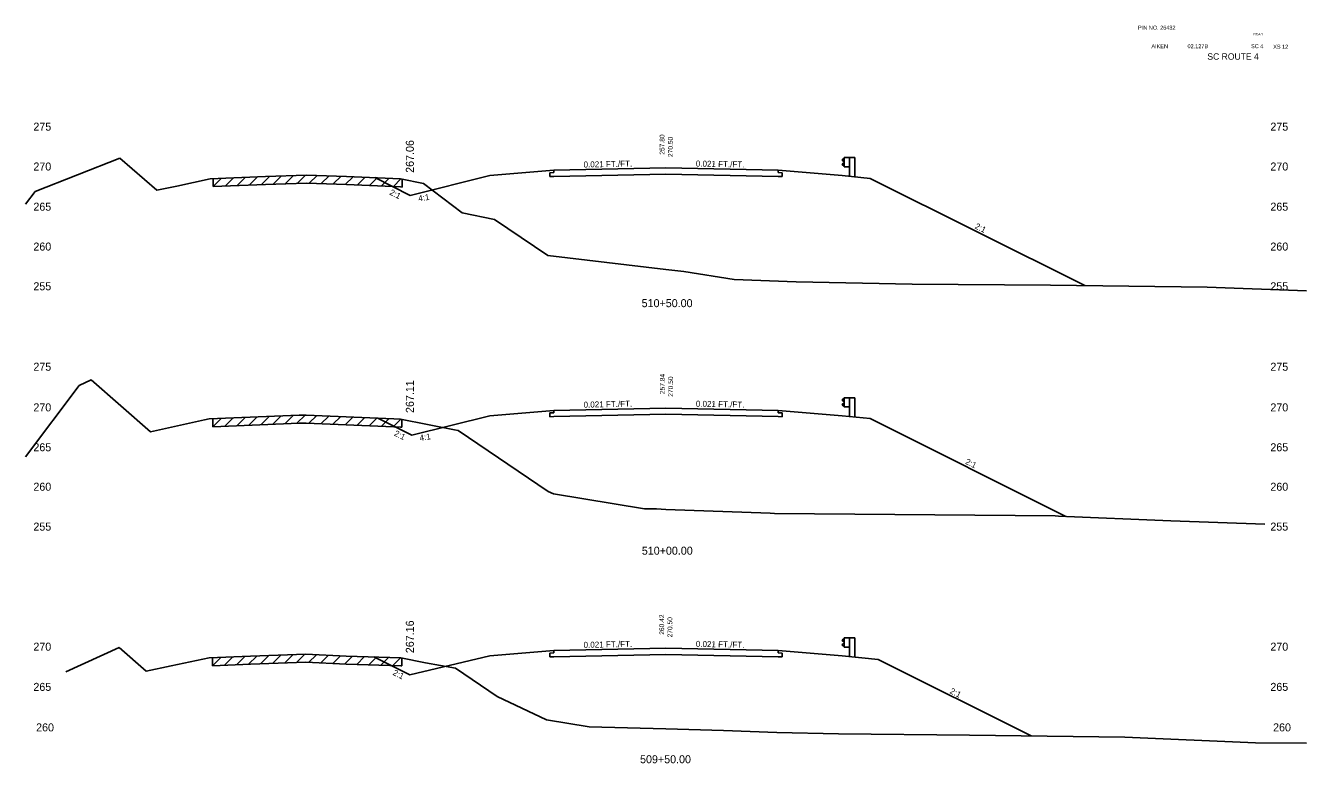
# Model space of a CAD drawing. Extents: x 883 to 1160, y 1002 to 4323.
# Drawn here: x 1000 to 1160, y 2276.1 to 2368.3 of the extents above; entities that cross this region are included whole.
import ezdxf

# ---------------------------------------------------------------- set-up
doc = ezdxf.new("R2010")
doc.units = 0
for name, color, linetype in [('Level 1', 7, 'Continuous'), ('Level 10', 7, 'Continuous'), ('Level 11', 7, 'Continuous'), ('Level 12', 7, 'Continuous'), ('Level 24', 7, 'Continuous'), ('Level 3', 7, 'Continuous'), ('Level 32', 7, 'Continuous'), ('Level 33', 7, 'Continuous'), ('Level 59', 7, 'Continuous'), ('Level 6', 7, 'Continuous'), ('Level 60', 7, 'Continuous'), ('Level 61', 7, 'Continuous'), ('Level 7', 7, 'Continuous')]:
    doc.layers.add(name, color=color, linetype=linetype)

msp = doc.modelspace()

# ---------------------------------------------------------------- linework, layer by layer
at = {"layer": 'Level 11'}
for p, q in [((1066, 2349.91), (1065.5, 2349.9)), ((1065.5, 2349.9), (1065.5, 2349.42)), ((1065.5, 2349.42), (1066, 2349.43)), ((1066, 2350.21), (1066, 2349.91)), ((1094, 2349.91), (1094, 2350.21)), ((1094.5, 2349.9), (1094, 2349.91)), ((1094, 2349.43), (1094.5, 2349.42)), ((1094.5, 2349.42), (1094.5, 2349.9)), ((1066, 2320.21), (1066, 2319.91)), ((1094, 2319.91), (1094, 2320.21)), ((1066, 2319.91), (1065.5, 2319.9)), ((1065.5, 2319.9), (1065.5, 2319.42)), ((1065.5, 2319.42), (1066, 2319.43)), ((1094.5, 2319.9), (1094, 2319.91)), ((1094, 2319.43), (1094.5, 2319.42)), ((1094.5, 2319.42), (1094.5, 2319.9)), ((1066, 2289.91), (1065.5, 2289.9)), ((1065.5, 2289.9), (1065.5, 2289.42)), ((1066, 2290.21), (1066, 2289.91)), ((1094, 2289.91), (1094, 2290.21)), ((1094.5, 2289.9), (1094, 2289.91)), ((1094.5, 2289.42), (1094.5, 2289.9)), ((1065.5, 2289.42), (1066, 2289.43)), ((1094, 2289.43), (1094.5, 2289.42))]:
    msp.add_line(p, q, dxfattribs=at)
at = {"layer": 'Level 12'}
for p, q in [((1080, 2349.72), (1066, 2349.43)), ((1094, 2349.43), (1080, 2349.72)), ((1080, 2319.72), (1066, 2319.43)), ((1094, 2319.43), (1080, 2319.72)), ((1080, 2289.72), (1066, 2289.43)), ((1094, 2289.43), (1080, 2289.72))]:
    msp.add_line(p, q, dxfattribs=at)
at = {"layer": 'Level 24'}
for p, q in [((1102.27, 2351.72), (1102, 2351.52)), ((1102, 2351.52), (1102, 2351.47)), ((1102, 2351.47), (1102.27, 2351.27)), ((1102, 2350.95), (1102.27, 2351.15)), ((1102, 2350.9), (1102, 2350.95)), ((1102.27, 2350.7), (1102, 2350.9)), ((1102.27, 2350.63), (1102.27, 2351.79)), ((1102.27, 2351.79), (1102.94, 2351.79)), ((1102.27, 2350.63), (1102.94, 2350.63)), ((1102.94, 2351.79), (1102.94, 2349.45)), ((1102.94, 2351.79), (1103.6, 2351.79)), ((1103.6, 2351.79), (1103.6, 2349.38)), ((1102.27, 2321.72), (1102, 2321.52)), ((1102.27, 2320.63), (1102.27, 2321.79)), ((1102.27, 2321.79), (1102.94, 2321.79)), ((1102.94, 2321.79), (1102.94, 2319.45)), ((1102.94, 2321.79), (1103.6, 2321.79)), ((1103.6, 2321.79), (1103.6, 2319.38)), ((1102, 2321.52), (1102, 2321.47)), ((1102, 2321.47), (1102.27, 2321.27)), ((1102, 2320.95), (1102.27, 2321.15)), ((1102, 2320.9), (1102, 2320.95)), ((1102.27, 2320.7), (1102, 2320.9)), ((1102.27, 2320.63), (1102.94, 2320.63)), ((1102.27, 2291.72), (1102, 2291.52)), ((1102, 2291.52), (1102, 2291.47)), ((1102, 2291.47), (1102.27, 2291.27)), ((1102.27, 2290.63), (1102.27, 2291.79)), ((1102.27, 2291.79), (1102.94, 2291.79)), ((1102.94, 2291.79), (1102.94, 2289.45)), ((1102.94, 2291.79), (1103.6, 2291.79)), ((1103.6, 2291.79), (1103.6, 2289.38)), ((1102, 2290.95), (1102.27, 2291.15)), ((1102, 2290.9), (1102, 2290.95)), ((1102.27, 2290.7), (1102, 2290.9)), ((1102.27, 2290.63), (1102.94, 2290.63))]:
    msp.add_line(p, q, dxfattribs=at)
at = {"layer": 'Level 59'}
for p, q in [((1066, 2350.21), (1080, 2350.5)), ((1080, 2350.5), (1094, 2350.21)), ((1066, 2320.21), (1080, 2320.5)), ((1080, 2320.5), (1094, 2320.21)), ((1066, 2290.21), (1080, 2290.5)), ((1080, 2290.5), (1094, 2290.21))]:
    msp.add_line(p, q, dxfattribs=at)
at = {"layer": 'Level 6'}
for p, q in [((1058, 2349.54), (1066, 2350.21)), ((1094, 2350.21), (1102, 2349.54)), ((1102, 2349.54), (1105.5, 2349.19)), ((1058, 2319.54), (1066, 2320.21)), ((1094, 2320.21), (1102, 2319.54)), ((1102, 2319.54), (1105.5, 2319.19)), ((1058, 2289.54), (1066, 2290.21)), ((1094, 2290.21), (1102, 2289.54)), ((1102, 2289.54), (1106.5, 2289.09))]:
    msp.add_line(p, q, dxfattribs=at)
at = {"layer": 'Level 60'}
for p, q in [((1001.18, 2347.53), (1011.79, 2351.72)), ((1011.79, 2351.72), (1016.39, 2347.7)), ((1018.89, 2348.23), (1023.07, 2349.14)), ((1023.07, 2349.14), (1029.98, 2349.42)), ((1029.98, 2349.42), (1035.08, 2349.6)), ((1035.08, 2349.6), (1040.09, 2349.43)), ((1040.09, 2349.43), (1046.84, 2349.13)), ((1046.84, 2349.13), (1049.69, 2348.56)), ((1000, 2345.96), (1001.18, 2347.53)), ((1016.39, 2347.7), (1018.89, 2348.23)), ((1049.69, 2348.56), (1054.54, 2344.88)), ((1054.54, 2344.88), (1058.59, 2344.06)), ((1058.59, 2344.06), (1065.23, 2339.56)), ((1065.23, 2339.56), (1080, 2337.81)), ((1080, 2337.81), (1082.21, 2337.54)), ((1082.21, 2337.54), (1088.53, 2336.54)), ((1088.53, 2336.54), (1096.28, 2336.28)), ((1096.28, 2336.28), (1110.74, 2335.97)), ((1110.74, 2335.97), (1128.03, 2335.84)), ((1128.03, 2335.84), (1147.59, 2335.59)), ((1147.59, 2335.59), (1160, 2335.12)), ((1000, 2314.41), (1006.68, 2323.32)), ((1006.68, 2323.32), (1008.19, 2324.02)), ((1008.19, 2324.02), (1015.59, 2317.54)), ((1015.59, 2317.54), (1022.35, 2319.03)), ((1022.35, 2319.03), (1022.95, 2319.15)), ((1022.95, 2319.15), (1034.17, 2319.6)), ((1034.17, 2319.6), (1035.03, 2319.63)), ((1035.03, 2319.63), (1045.99, 2319.14)), ((1045.99, 2319.14), (1046.85, 2319.12)), ((1046.85, 2319.12), (1053.58, 2317.78)), ((1053.58, 2317.78), (1054.02, 2317.7)), ((1054.02, 2317.7), (1065.29, 2310.07)), ((1065.29, 2310.07), (1065.93, 2309.77)), ((1065.93, 2309.77), (1077.32, 2307.93)), ((1077.32, 2307.93), (1078.81, 2307.89)), ((1078.81, 2307.89), (1080, 2307.84)), ((1080, 2307.84), (1093.01, 2307.36)), ((1093.01, 2307.36), (1093.55, 2307.34)), ((1093.55, 2307.34), (1128.62, 2307.02)), ((1128.62, 2307.02), (1129.03, 2307.01)), ((1129.03, 2307.01), (1143.08, 2306.43)), ((1143.08, 2306.43), (1154.81, 2305.98)), ((1005.03, 2287.54), (1011.67, 2290.6)), ((1011.67, 2290.6), (1015.07, 2287.62)), ((1028.09, 2289.5), (1035.01, 2289.74)), ((1035.01, 2289.74), (1040.06, 2289.52)), ((1015.07, 2287.62), (1018.19, 2288.3)), ((1018.19, 2288.3), (1022.92, 2289.29)), ((1022.92, 2289.29), (1028.09, 2289.5)), ((1040.06, 2289.52), (1046.86, 2289.3)), ((1046.86, 2289.3), (1049.97, 2288.68)), ((1049.97, 2288.68), (1053.7, 2288)), ((1053.7, 2288), (1058.92, 2284.46)), ((1058.92, 2284.46), (1065.08, 2281.55)), ((1065.08, 2281.55), (1070.39, 2280.69)), ((1070.39, 2280.69), (1080, 2280.42)), ((1080, 2280.42), (1087.2, 2280.21)), ((1087.2, 2280.21), (1093.83, 2279.97)), ((1093.83, 2279.97), (1101.55, 2279.8)), ((1101.55, 2279.8), (1117.91, 2279.65)), ((1117.91, 2279.65), (1137.3, 2279.38)), ((1137.3, 2279.38), (1153.66, 2278.7)), ((1153.66, 2278.7), (1160, 2278.65))]:
    msp.add_line(p, q, dxfattribs=at)
at = {"layer": 'Level 61'}
for p, q in [((1024.48, 2349.2), (1023.44, 2348.16)), ((1023.44, 2349.16), (1023.44, 2348.16)), ((1025.98, 2349.26), (1024.94, 2348.22)), ((1027.48, 2349.32), (1026.44, 2348.28)), ((1028.98, 2349.38), (1027.94, 2348.34)), ((1030.48, 2349.44), (1029.44, 2348.4)), ((1031.98, 2349.49), (1030.94, 2348.45)), ((1033.48, 2349.54), (1032.44, 2348.51)), ((1034.98, 2349.6), (1033.94, 2348.56)), ((1036.41, 2349.56), (1035.44, 2348.59)), ((1037.91, 2349.5), (1036.94, 2348.54)), ((1039.41, 2349.45), (1038.44, 2348.49)), ((1040.9, 2349.39), (1039.94, 2348.44)), ((1042.4, 2349.33), (1041.44, 2348.37)), ((1043.9, 2349.26), (1042.94, 2348.3)), ((1045.4, 2349.2), (1044.44, 2348.24)), ((1046.89, 2349.12), (1045.94, 2348.17)), ((1047.02, 2348.1), (1047.02, 2349.1)), ((1023.44, 2348.16), (1029.98, 2348.42)), ((1029.98, 2348.42), (1035.08, 2348.6)), ((1035.08, 2348.6), (1040.09, 2348.43)), ((1040.09, 2348.43), (1046.84, 2348.13)), ((1046.84, 2348.13), (1047.02, 2348.1)), ((1024.44, 2319.21), (1023.4, 2318.17)), ((1023.4, 2319.17), (1023.4, 2318.17)), ((1023.4, 2318.17), (1034.17, 2318.6)), ((1025.94, 2319.27), (1024.9, 2318.23)), ((1027.44, 2319.33), (1026.4, 2318.29)), ((1028.94, 2319.39), (1027.9, 2318.35)), ((1030.44, 2319.45), (1029.4, 2318.41)), ((1031.94, 2319.51), (1030.9, 2318.47)), ((1033.44, 2319.57), (1032.4, 2318.53)), ((1034.94, 2319.62), (1033.9, 2318.59)), ((1034.17, 2318.6), (1035.03, 2318.63)), ((1035.03, 2318.63), (1045.99, 2318.14)), ((1036.36, 2319.57), (1035.4, 2318.61)), ((1037.86, 2319.5), (1036.9, 2318.54)), ((1039.36, 2319.44), (1038.4, 2318.48)), ((1040.86, 2319.37), (1039.9, 2318.41)), ((1042.36, 2319.3), (1041.4, 2318.35)), ((1043.86, 2319.24), (1042.9, 2318.28)), ((1045.36, 2319.17), (1044.4, 2318.21)), ((1046.86, 2319.11), (1045.9, 2318.15)), ((1047, 2318.09), (1047, 2319.09)), ((1045.99, 2318.14), (1046.85, 2318.12)), ((1046.85, 2318.12), (1047, 2318.09)), ((1031.89, 2289.63), (1030.86, 2288.59)), ((1033.39, 2289.68), (1032.36, 2288.65)), ((1034.89, 2289.74), (1033.86, 2288.7)), ((1036.32, 2289.68), (1035.36, 2288.73)), ((1037.82, 2289.62), (1036.86, 2288.66)), ((1024.4, 2289.35), (1023.36, 2288.31)), ((1023.36, 2289.31), (1023.36, 2288.31)), ((1023.36, 2288.31), (1028.09, 2288.5)), ((1025.9, 2289.41), (1024.86, 2288.37)), ((1027.4, 2289.47), (1026.36, 2288.43)), ((1028.9, 2289.52), (1027.86, 2288.49)), ((1028.09, 2288.5), (1035.01, 2288.74)), ((1030.39, 2289.58), (1029.36, 2288.54)), ((1035.01, 2288.74), (1040.06, 2288.52)), ((1039.32, 2289.55), (1038.36, 2288.59)), ((1040.82, 2289.5), (1039.86, 2288.53)), ((1040.06, 2288.52), (1046.86, 2288.3)), ((1042.33, 2289.45), (1041.36, 2288.48)), ((1043.83, 2289.4), (1042.86, 2288.43)), ((1045.33, 2289.35), (1044.36, 2288.38)), ((1046.83, 2289.3), (1045.86, 2288.33)), ((1046.86, 2288.3), (1046.98, 2288.28)), ((1046.98, 2288.28), (1046.98, 2289.28))]:
    msp.add_line(p, q, dxfattribs=at)
at = {"layer": 'Level 7'}
for p, q in [((1043.61, 2349.28), (1048.05, 2347.06)), ((1058, 2349.54), (1048.05, 2347.06)), ((1105.5, 2349.19), (1132.31, 2335.79)), ((1044, 2319.23), (1048.25, 2317.11)), ((1058, 2319.54), (1048.25, 2317.11)), ((1105.5, 2319.19), (1129.94, 2306.97)), ((1043.49, 2289.41), (1048, 2287.16)), ((1048, 2287.16), (1058, 2289.54)), ((1106.5, 2289.09), (1125.6, 2279.54))]:
    msp.add_line(p, q, dxfattribs=at)

# ---------------------------------------------------------------- texts
at = {"layer": 'Level 1'}
for s, height, p in [('PIN NO. 26432', 0.5, (1138.97, 2367.76)), ('AIKEN', 0.5, (1140.64, 2365.45)), ('02.127B', 0.5, (1145.15, 2365.45)), ('SC ROUTE 4', 0.8, (1147.63, 2364.01)), ('SC 4', 0.5, (1153.09, 2365.45)), ('XS 12', 0.5, (1155.85, 2365.39)), ('510+50.00', 1, (1076.96, 2333.1)), ('510+00.00', 1, (1076.98, 2302.18)), ('509+50.00', 1, (1076.76, 2276.13))]:
    msp.add_text(s, height=height, dxfattribs=at).set_placement(p)
at = {"layer": 'Level 10'}
for s, p in [('257.80', (1079.81, 2352.15)), ('257.84', (1079.84, 2322.24)), ('260.42', (1079.77, 2292.18))]:
    msp.add_text(s, height=0.6, rotation=90, dxfattribs=at).set_placement(p)
at = {"layer": 'Level 3'}
for s, height, p in [('ROAD', 0.3, (1153.38, 2367.04)), (' 275', 1, (1000.6, 2355.15)), (' 275', 1, (1155.13, 2355.15)), (' 270', 1, (1000.6, 2350.17)), (' 270', 1, (1155.13, 2350.17)), (' 265', 1, (1000.6, 2345.15)), (' 265', 1, (1155.13, 2345.15)), (' 260', 1, (1000.6, 2340.17)), (' 260', 1, (1155.13, 2340.17)), (' 255', 1, (1000.6, 2335.21)), (' 255', 1, (1155.13, 2335.21)), (' 275', 1, (1000.6, 2325.16)), (' 275', 1, (1155.13, 2325.16)), (' 270', 1, (1000.6, 2320.08)), (' 270', 1, (1155.13, 2320.08)), (' 265', 1, (1000.6, 2315.1)), (' 265', 1, (1155.13, 2315.1)), (' 260', 1, (1000.6, 2310.17)), (' 260', 1, (1155.13, 2310.17)), (' 255', 1, (1000.6, 2305.19)), (' 255', 1, (1155.13, 2305.19)), (' 270', 1, (1000.6, 2290.19)), (' 270', 1, (1155.13, 2290.19)), (' 265', 1, (1000.6, 2285.17)), (' 265', 1, (1155.13, 2285.17)), (' 260', 1, (1000.94, 2280.11)), (' 260', 1, (1155.47, 2280.11))]:
    msp.add_text(s, height=height, dxfattribs=at).set_placement(p)
at = {"layer": 'Level 32'}
for s, rotation, p in [('0.021 FT./FT.', 1.1916, (1069.71, 2350.54)), ('0.021 FT./FT.', 358.8084, (1083.72, 2350.67)), ('2:1', 333.435, (1045.39, 2347.2)), ('4:1', 9.4623, (1049.12, 2346.29)), ('2:1', 333.435, (1118.51, 2342.97)), ('0.021 FT./FT.', 1.1916, (1069.71, 2320.54)), ('0.021 FT./FT.', 358.8084, (1083.72, 2320.67)), ('2:1', 333.435, (1045.96, 2317.09)), ('4:1', 9.4623, (1049.28, 2316.38)), ('2:1', 333.435, (1117.32, 2313.56)), ('0.021 FT./FT.', 1.1916, (1069.71, 2290.54)), ('0.021 FT./FT.', 358.8084, (1083.72, 2290.67)), ('2:1', 333.435, (1045.8, 2287.21)), ('2:1', 333.435, (1115.39, 2284.91))]:
    msp.add_text(s, height=0.75, rotation=rotation, dxfattribs=at).set_placement(p)
at = {"layer": 'Level 33'}
for s, p in [('267.06', (1048.5, 2349.88)), ('267.11', (1048.5, 2319.88)), ('267.16', (1048.5, 2289.88))]:
    msp.add_text(s, height=1, rotation=90, dxfattribs=at).set_placement(p)
at = {"layer": 'Level 59'}
for p in [(1080.85, 2351.62), (1080.88, 2321.68), (1080.79, 2291.62)]:
    msp.add_text(' 270.50', height=0.6, rotation=90, dxfattribs=at).set_placement(p)

doc.saveas('drawing.dxf')
